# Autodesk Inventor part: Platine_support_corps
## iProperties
Shininess: 64.0
Length Units: 11269
Angle Units: 11279
Time Units: 11290
Mass Units: 11283
Length Display Precision: 3
Angle Display Precision: 2
Compacted: True
Part Number: Platine_support_corps
Document SubType Name: Modeling
Created: 2008-02
Material: Par défaut
Designer: Pascal
Density: 1 g/cm^3
Density: 0.0
Volumn: 0.0
Area: 0.0
PropertySet Name: Model Information
Control State: 0
Master: False
Checked Out: False
DESIGNATION: pièce
Author: Pascal
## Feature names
1. Extrusion1
2. Chanfrein1 [Chamfer]
3. Extrusion2
4. Réseau rectangulaire1 [Rectangular Pattern]
